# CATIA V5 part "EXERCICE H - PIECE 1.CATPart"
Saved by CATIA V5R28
Part number: Exercice H - pièce 1
Bounding box of the stored display mesh (mm): x 0 to 8, y -8 to 8, z 0 to 26
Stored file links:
  \\stisrv.epfl.ch\sti-sgm\sgm-ens\soubiell\Enseignement\ME-101-106 - Construction Mécanique I\1. Supports de cours\Z. Archives\2020\SW3\Modèles 3D exercice H\EXERCICE H - PIECE 1.CATPart
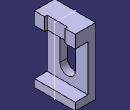
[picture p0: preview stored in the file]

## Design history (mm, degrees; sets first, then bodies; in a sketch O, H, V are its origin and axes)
Body1 (main body)
  Sketch1 on zx-plane, origin (0, 0, 0), H (-1, 0, 0), V (0, 0, 1)
    line L1 (0, 0) -> (0, 26)
    line L2 (0, 26) -> (-8, 26)
    line L3 (-8, 26) -> (-8, 21)
    line L4 (-8, 21) -> (-3, 21)
    line L5 (-3, 21) -> (-3, 3)
    line L6 (-3, 3) -> (-8, 3)
    point P6 (-8, 3)
    line L7 (-8, 3) -> (-8, 0)
    point P7 (-8, 0)
    line L8 (-8, 0) -> (0, 0)
    length L1 = 26
    length L7 = 3
    length L8 = 8
    distance L5 L1 = 3
    length L3 = 5
    vertical: L1 V, L3 V, L5 V, L7 V
    horizontal: L2 H, L4 H, L6 H, L8 H
    coincidence: P6 L3, P7 H
  Pad1: profile Sketch1, direction (0, 1, 0), length 8, mirrored extent
  Sketch2 on face of Pad1 from Sketch1.L2, origin (0, 0, 26), H (1, 0, 0), V (0, 1, 0)
    line L1 (8, 4) -> (7, 4)
    line L2 (7, 4) -> (7, -4)
    line L3 (7, -4) -> (8, -4)
    line L4 (8, -4) -> (8, 4)
    reference projected line E1 (8, -8) -> (8, 8) from edge [face of Pad1 from Sketch1.L3 | face of Pad1 from Sketch1.L2]
    reference projected line E2 (0, 8) -> (8, 8) from edge [face of Pad1 from Sketch1.L2 | end face of Pad1]
    reference projected line E3 (0, -8) -> (8, -8) from edge [start face of Pad1 | face of Pad1 from Sketch1.L2]
    distance E2 L1 = 4
    distance L3 E3 = 4
    length L1 = 1
    horizontal: L1 H, L3 H
    vertical: L2 V, L4 V
    coincidence: L4 E1
  Pocket1: profile Sketch2, direction (0, 0, -1), through (limit type 6)
  Sketch3 on face of Pad1 from Sketch1.L5, origin (3, 0, 0), H (0, 1, 0), V (0, 0, 1)
    construction line L1 (0, 16.5) -> (0, 8.5)
    point P1 (0, 16.5)
    point P2 (0, 8.5)
    line L2 (3, 16.5) -> (3, 8.5)
    line L3 (-3, 8.5) -> (-3, 16.5)
    arc A1 centre (0, 8.5) radius 3 from (3, 8.5) to (-3, 8.5) cw
    arc A2 centre (0, 16.5) radius 3 from (-3, 16.5) to (3, 16.5) cw
    reference projected line E1 (-8, 3) -> (8, 3) from edge [face of Pad1 from Sketch1.L7 | face of Pad1 from Sketch1.L6]
    distance L1 L2 = 3
    distance P2 E1 = 5.5
    length L2 = 8
    coincidence: P1 V
    vertical: L1 V
    tangency: A1 L2, A2 L2, A1 L3, A2 L3
  Pocket2: profile Sketch3, direction (-1, 0, 0), through (limit type 6)
  Sketch4 "PLAN DE COUPE A-A" on zx-plane, origin (0, 0, 0), H (-1, 0, 0), V (0, 0, 1)
    line L1 (0, 0) -> (-8, 0)
    line L2 (-8, 0) -> (-8, 26)
    line L3 (-8, 26) -> (0, 26)
    line L4 (0, 26) -> (0, 0)
    horizontal: L1 H, L3 H
    vertical: L2 V, L4 V
  Pocket3 "COUPE A-A": profile Sketch4, direction (0, -1, 0), through (limit type 6)
Current feature: Pocket2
